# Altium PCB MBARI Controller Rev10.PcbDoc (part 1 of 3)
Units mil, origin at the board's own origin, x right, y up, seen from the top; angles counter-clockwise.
Board outline 10420.2 x 10420.2 mil, 2 copper layers (Top Layer, Bottom Layer); 284 components, 200 nets, 1050 pads, 245 vias.
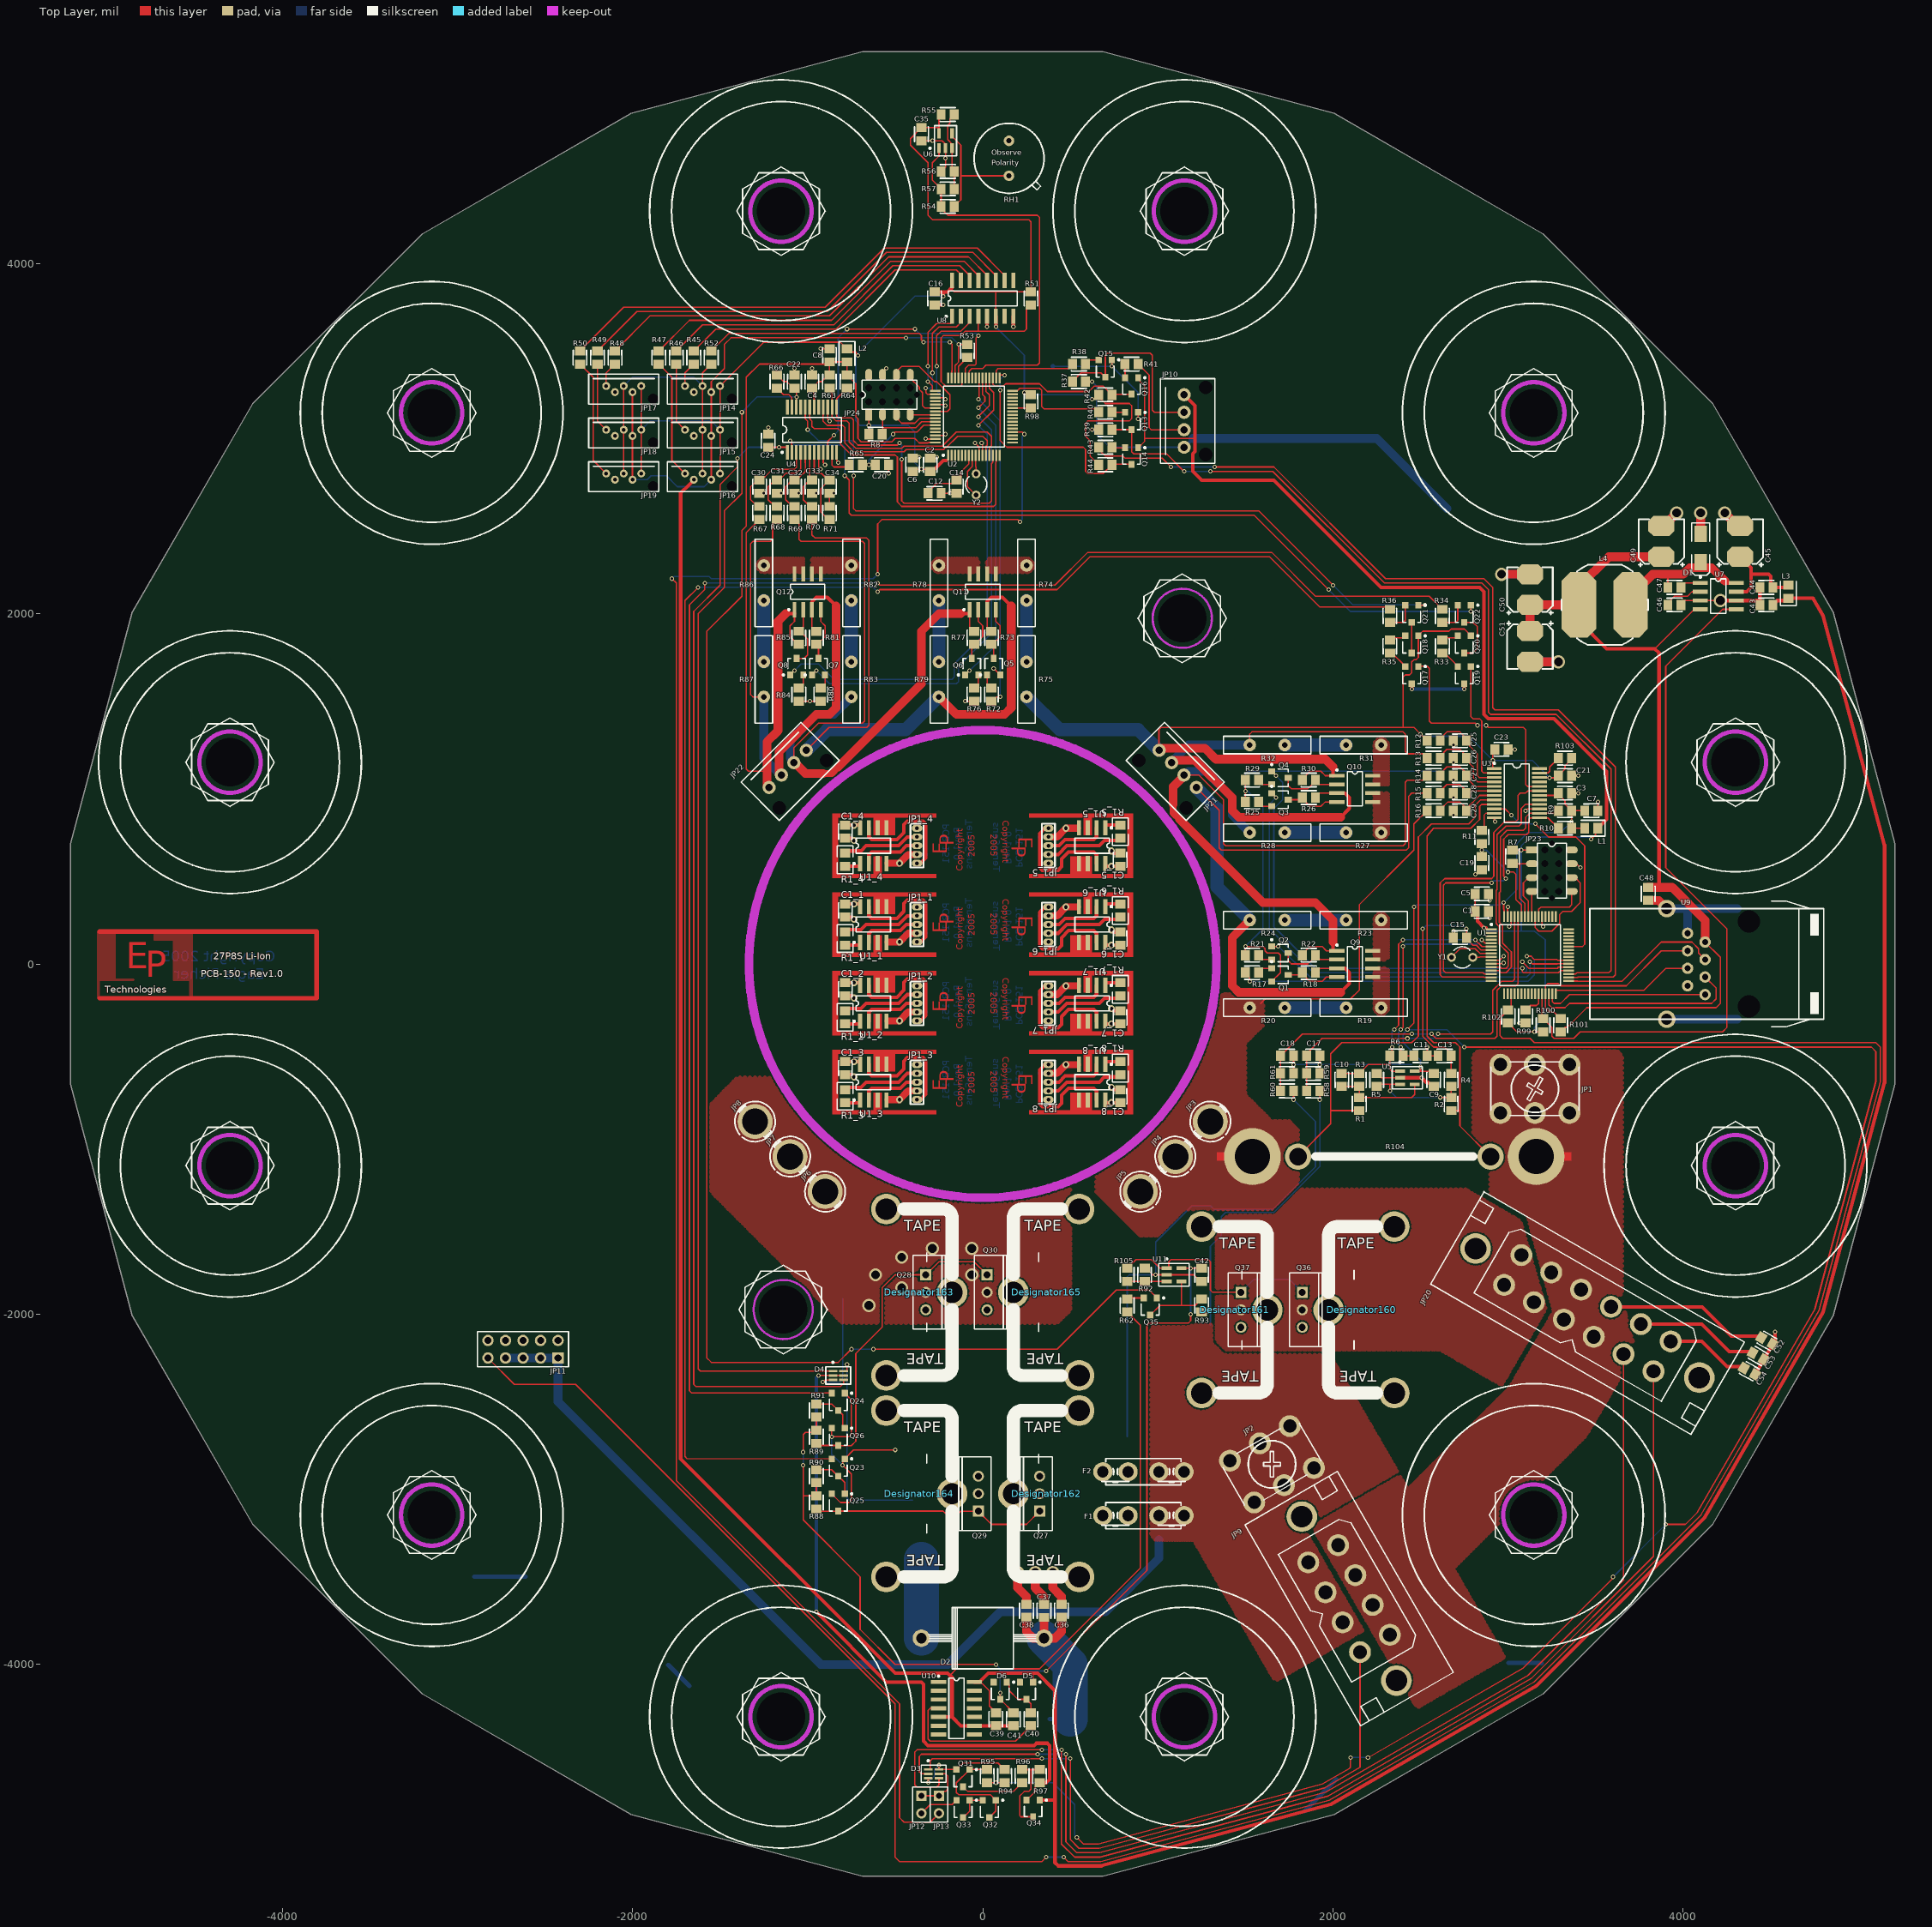
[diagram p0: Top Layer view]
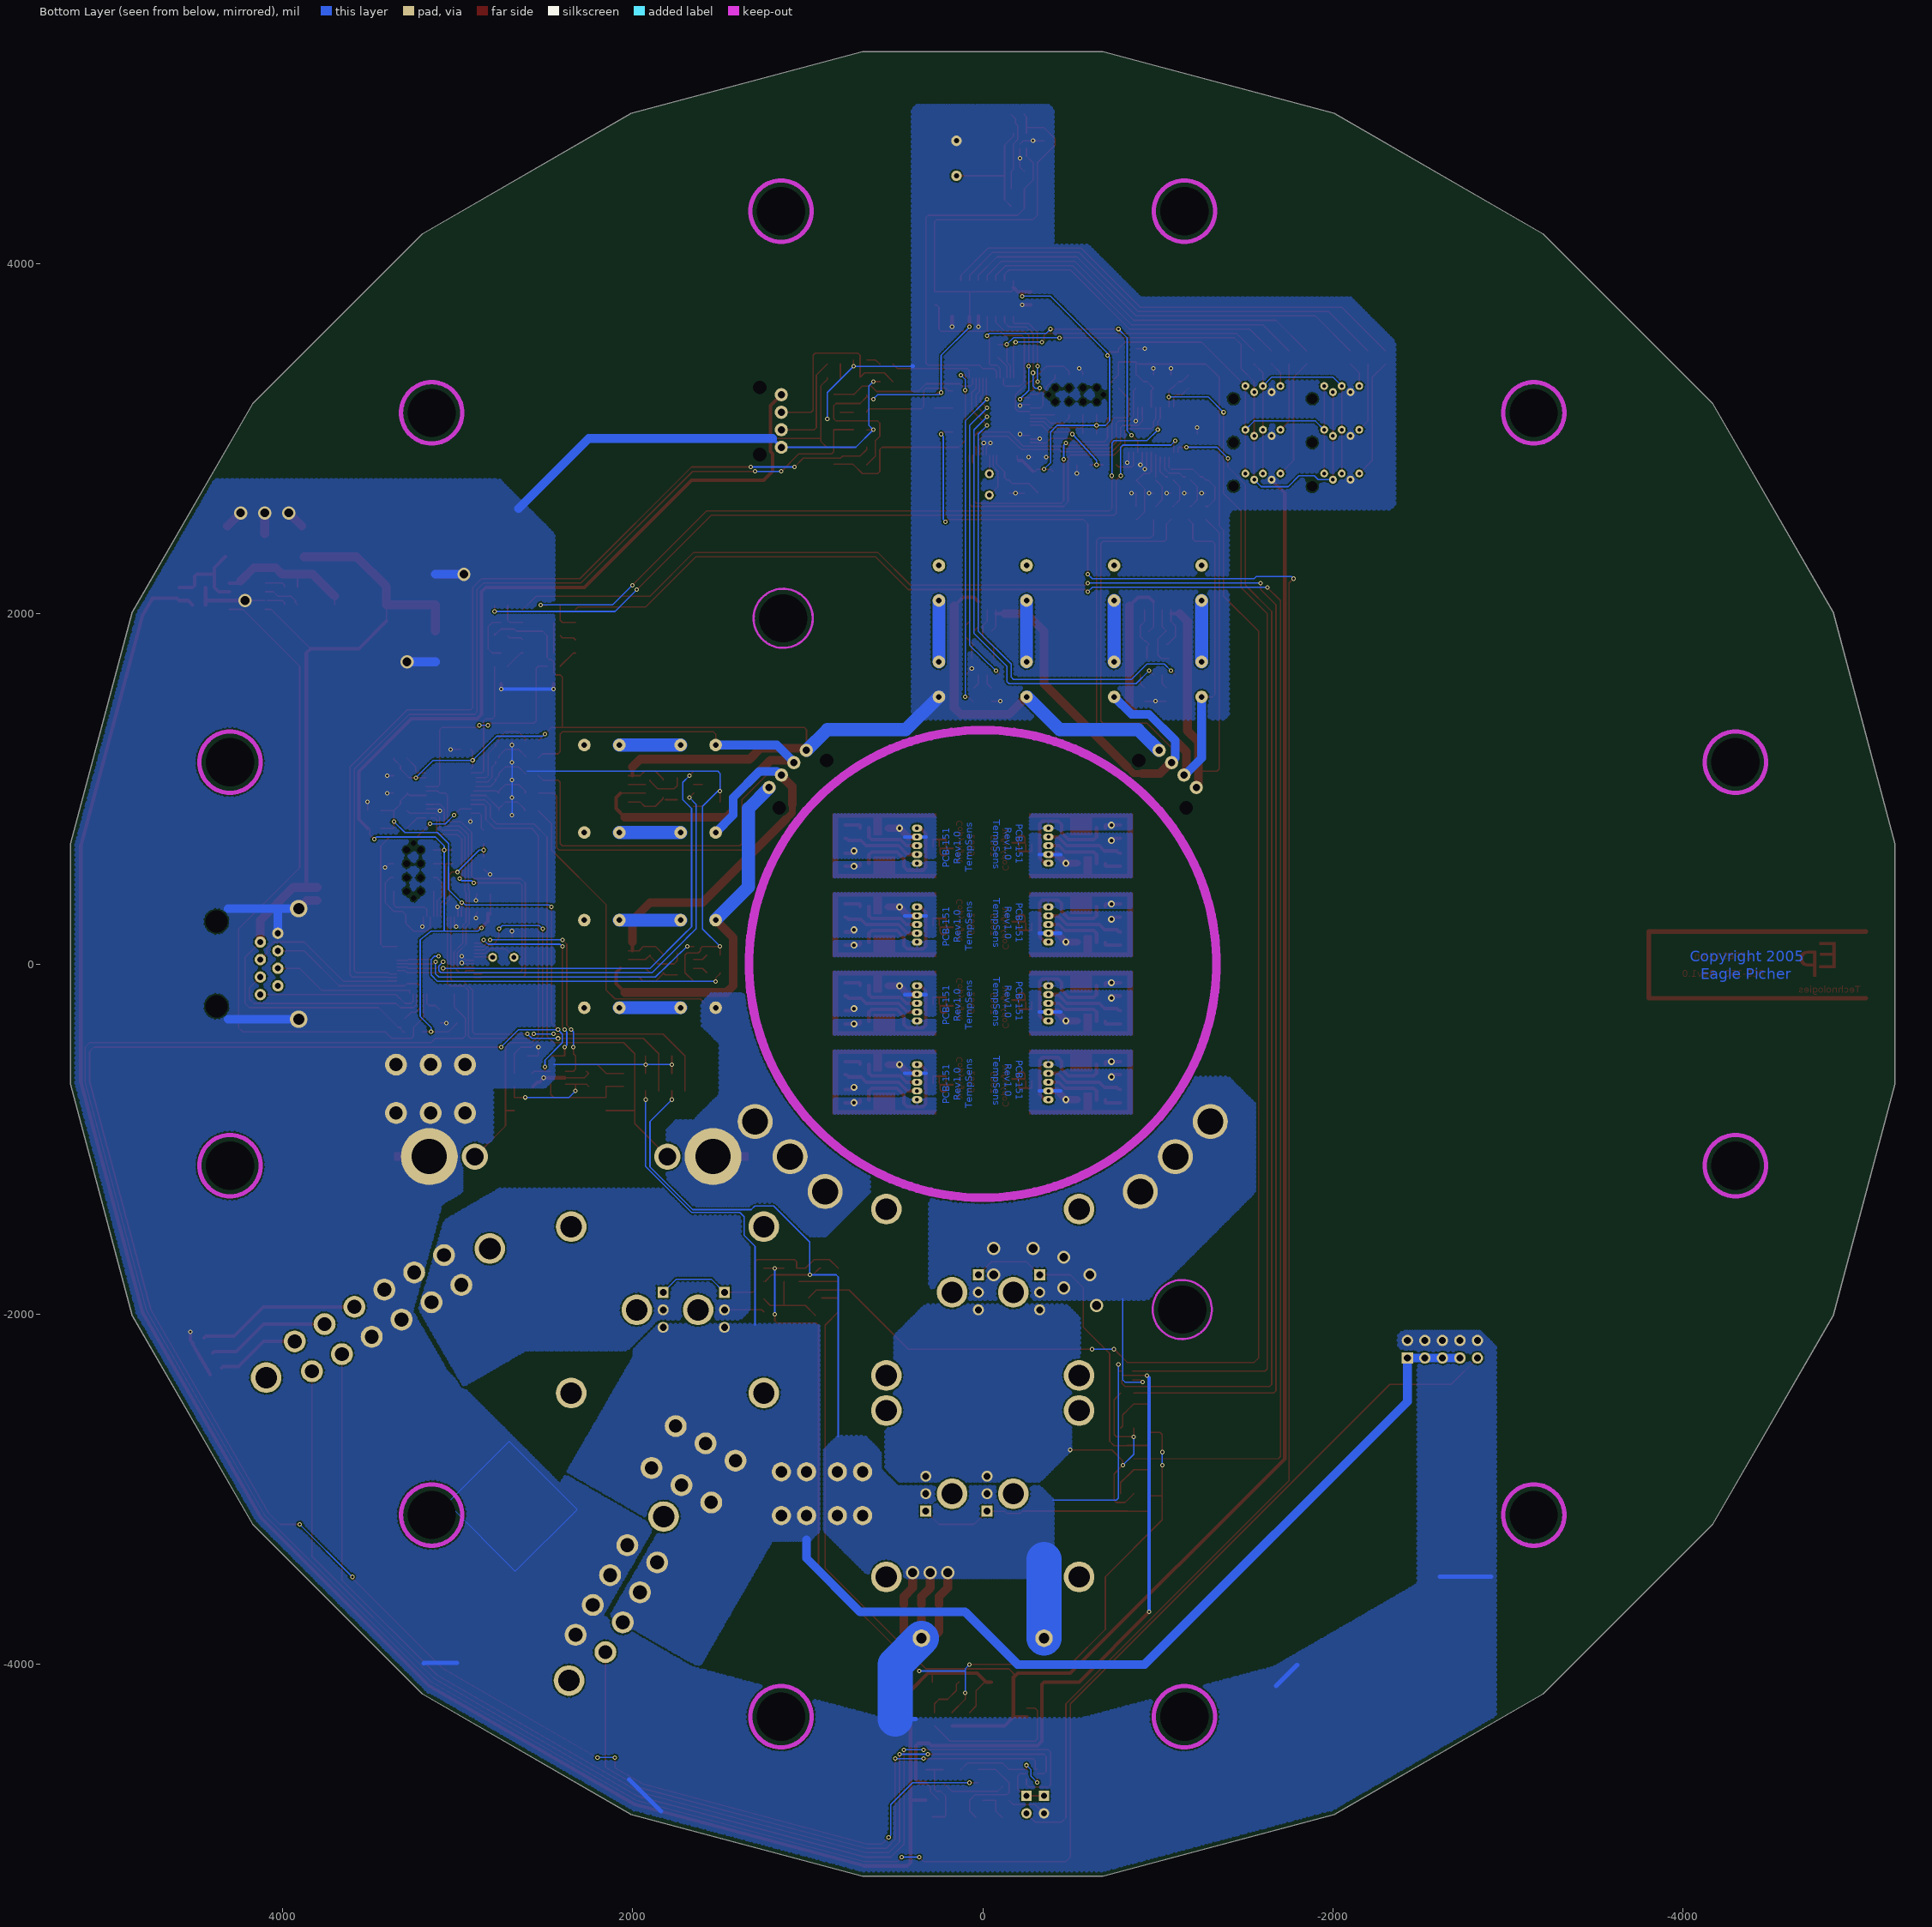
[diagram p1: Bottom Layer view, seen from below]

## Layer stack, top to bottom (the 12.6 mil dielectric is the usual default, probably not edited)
Top Layer: signal copper 1.4
Dielectric: dielectric 12.6, FR-4, Dk 4.8
Bottom Layer: signal copper 1.4

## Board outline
-4854.71,-2011.6 cw(c-4850.37,-2009.09) -4855.12,-2010.67 cw(c-4850.37,-2009.09) -4855.21,-2010.39 -5209.93,-686.56 cw(c-5205.09,-685.26) -5210.1,-685.26 ccw(c-5205.09,-685.26) -5209.93,-686.56 -5210.1,-685.26 -5210.1,685.26 cw(c-5205.09,685.26) -5209.92,686.58 -4855.21,2010.39 cw(c-4850.37,2009.09) -4854.7,2011.62 -4169.45,3198.5 cw(c-4165.1,3196) -4168.65,3199.54 cw(c-4165.1,3196) -4168.63,3199.56 -4168.65,3199.54 -3199.54,4168.65 cw(c-3196,4165.1) -3198.48,4169.46 -2011.6,4854.71 cw(c-2009.09,4850.37) -2010.67,4855.12 cw(c-2009.09,4850.37) -2010.39,4855.21 -686.56,5209.93 cw(c-685.26,5205.08) -685.26,5210.1 ccw(c-685.26,5205.08) -686.56,5209.93 -685.26,5210.1 685.26,5210.1 cw(c685.26,5205.08) 686.58,5209.92 2010.39,4855.21 cw(c2009.09,4850.37) 2011.62,4854.7 3198.5,4169.45 cw(c3196,4165.1) 3199.54,4168.65 cw(c3196,4165.1) 3199.56,4168.63 3199.54,4168.65 4168.65,3199.54 cw(c4165.1,3196) 4169.46,3198.48 4854.71,2011.6 cw(c4850.37,2009.09) 4855.21,2010.37 4855.21,2010.39 ccw(c4850.37,2009.09) 4854.71,2011.6 4855.21,2010.37 5209.93,686.56 cw(c5205.08,685.26) 5210.1,685.26 ccw(c5205.08,685.26) 5209.93,686.56 5210.1,685.26 5210.1,-685.26 cw(c5205.08,-685.26) 5209.95,-686.48 cw(c5205.08,-685.26) 5209.93,-686.56 5209.93,-686.57 ccw(c5205.08,-685.26) 5209.93,-686.55 5209.93,-686.57 4855.21,-2010.39 cw(c4850.37,-2009.09) 4854.7,-2011.62 4854.71,-2011.6 ccw(c4850.37,-2009.09) 4855.21,-2010.39 4854.7,-2011.62 4169.45,-3198.5 cw(c4165.1,-3196) 4168.65,-3199.54 ccw(c4165.1,-3196) 4169.45,-3198.5 4168.65,-3199.54 cw(c4165.1,-3196) 4168.63,-3199.56 4168.65,-3199.54 3199.54,-4168.65 cw(c3196,-4165.1) 3198.48,-4169.46 3198.5,-4169.45 ccw(c3196,-4165.1) 3199.54,-4168.65 3198.48,-4169.46 2011.6,-4854.71 cw(c2009.09,-4850.37) 2010.67,-4855.12 ccw(c2009.09,-4850.37) 2011.6,-4854.71 2010.67,-4855.12 cw(c2009.09,-4850.37) 2010.39,-4855.21 ccw(c2009.09,-4850.37) 2010.67,-4855.12 2010.39,-4855.21 686.56,-5209.93 cw(c685.26,-5205.09) 685.26,-5210.1 ccw(c685.26,-5205.09) 686.56,-5209.93 685.26,-5210.1 -685.26,-5210.1 cw(c-685.26,-5205.09) -686.58,-5209.92 -2010.39,-4855.21 cw(c-2009.09,-4850.37) -2011.62,-4854.7 -3198.5,-4169.45 cw(c-3196,-4165.1) -3199.54,-4168.65 cw(c-3196,-4165.1) -3199.56,-4168.63 -3199.54,-4168.65 -4168.65,-3199.54 cw(c-4165.1,-3196) -4169.46,-3198.48

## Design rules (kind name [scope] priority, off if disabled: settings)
Clearance "Clearance Overlay" [(OnLayer('Top Overlay'))] p1: gap=-20
Clearance "Clearance U1 & U2" [(InComponent('U1')) OR (InComponent('U2')) vs (InComponent('U1')) OR (InComponent('U2'))] p2: gap=7.5
Clearance [All] p3: gap=8
ComponentClearance [All] p1: gap=10 collisioncheckmode=0
HoleSize [All] p1: absolutevalues=TRUE maxlimit=275 minlimit=15 maxpercent=80.000 minpercent=20.000
PlaneClearance [All] p1: clearance=35
PolygonConnect [All] p1: connectstyle=Direct reliefconductorwidth=10 reliefentries=4 polygonreliefangle="90 Angle"
RoomDefinition "MBARI Controller Rev10b" [InComponentClass('MBARI Controller Rev10b')] p1: confinementstyle=ConfineIn formatcopy=TRUE outline -7000,-7000 -5000,-7000 -5000,-6000 -7000,-6000
RoutingCorners [All] p1: cornerstyle=45-Degree minsetback=12.5 maxsetback=100
RoutingVias [All] p1: holewidth=15 width=25 viastyle="Through Hole" minholewidth=15 minwidth=25 maxholewidth=100 maxwidth=50
SolderMaskExpansion [All] p1: expansion=4
TestPointUsage [All] p1: valid=0 allowmultiple=FALSE
Testpoint [All] p1: side=15 testpointundercomponent=TRUE minsize=40 maxsize=100 preferedsize=60 minholesize=0 maxholesize=40 preferedholesize=32 testpointgrid=1 style=1023 order=1234567890
Width [All] p1: maxlimit=200 minlimit=8 preferedwidth=8
14 further rules are at their usual default settings.

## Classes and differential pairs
component class "MBARI Controller Rev10a": C1 C2 C3 C4 C5 C6 C7 C8 C9 C10 C11 C12 C13 C14 C15 C16 C17 C18 C19 C20 C21 C22 C23 C24 C25 C26 C27 C28 C29 C30 C31 C32 C33 C34 C35 C36 C37 C38 C39 C40 C41 C42 C43 C44 C45 C46 C47 C48 C49 C50 C51 C52 C53 C54 D1 D2 D3 D4 D5 D6 F1 F2 JP1 JP2 JP3 JP4 JP5 JP6 JP7 JP8 JP9 JP10 JP11 JP12 JP13 JP14 JP15 JP16 JP17 JP18 JP19 JP20 JP20x JP21 JP22 JP23 JP24 L1 L2 L3 L4 Q1 Q2 Q3 Q4 Q5 Q6 Q7 Q8 Q9 Q10 Q11 Q12 Q13 Q14 Q15 Q16 Q17 Q18 Q19 Q20 Q21 Q22 Q23 Q24 Q25 Q26 Q27 Q28 Q29 Q30 Q31 Q32 Q33 Q34 Q35 Q36 Q37 R1 R2 R3 R4 R5 R6 R7 R8 R9 R10 R11 R12 R13 R14 R15 R16 R17 R18 R19 R20 R21 R22 R23 R24 R25 R26 R27 R28 R29 R30 R31 R32 R33 R34 R35 R36 R37 R38 R39 R40 R41 R42 R43 R44 R45 R46 R47 R48 R49 R50 R51 R52 R53 R54 R55 R56 R57 R58 R59 R60 R61 R62 R63 R64 R65 R66 R67 R68 R69 R70 R71 R72 R73 R74 R75 R76 R77 R78 R79 R80 R81 R82 R83 R84 R85 R86 R87 R88 R89 R90 R91 R92 R93 R94 R95 R96 R97 R98 R99 R100 R101 R102 R103 R104 R105 RH1 U1 U2 U3 U4 U5 U6 U7 U8 U9 U10 U11 Y1 Y2

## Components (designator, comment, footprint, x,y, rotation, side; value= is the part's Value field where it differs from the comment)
C1 "C0805" 0805 2850,300 r180 top
C1_1 "C0805" 0805 -785,305 r90 top (schematic designator C1)
C1_2 "C0805" 0805 -785,-145 r90 top (schematic designator C1)
C1_3 "C0805" 0805 -785,-595 r90 top (schematic designator C1)
C1_4 "C0805" 0805 -785,755 r90 top (schematic designator C1)
C1_5 "C0805" 0805 785,595 r270 top (schematic designator C1)
C1_6 "C0805" 0805 785,145 r270 top (schematic designator C1)
C1_7 "C0805" 0805 785,-305 r270 top (schematic designator C1)
C1_8 "C0805" 0805 785,-755 r270 top (schematic designator C1)
C2 "C0805" 0805 -300,2850 r270 top
C3 "C0805" 0805 3325,975 r180 top
C4 "C0805" 0805 -975,3325 r270 top
C5 "C0805" 0805 2850,400 r0 top
C6 "C0805" 0805 -400,2850 r90 top
C7 "C0805" 0805 3475,875 r0 top
C8 "C0805" 0805 -875,3475 r90 top
C9 "C0805" 0805 2575,-662.5 r90 top locked
C10 "C0805" 0805 2050,-662.5 r90 top locked
C11 "C0805" 0805 2500,-525 r0 top
C12 "C0805" 0805 -275,2687.5 r0 top
C13 "C0805" 0805 2637.5,-525 r180 top locked
C14 "C0805" 0805 -150,2725 r90 top
C15 "C0805" 0805 2725,150 r0 top
C16 "C0805" 0805 -275,3800.1 r90 top
C17 "C0805" 0805 1887.6,-525 r180 top locked
C18 "C0805" 0805 1737.6,-525 r180 top locked
C19 "C0805" 0805 2850,575 r90 top
C20 "C0805" 0805 -574.9,2850 r180 top
C21 "C0805" 0805 3325.1,1075 r180 top
C22 "C0805" 0805 -1075,3325 r270 top
C23 "C0805" 0805 2962.4,1225 r180 top locked
C24 "C0805" 0805 -1225,2987.4 r270 top locked
C25 "C0805" 0805 2725,1275 r0 top
C26 "C0805" 0805 2725,1175 r0 top
C27 "C0805" 0805 2725,1075 r0 top
C28 "C0805" 0805 2725,975 r0 top
C29 "C0805" 0805 2725,875 r0 top
C30 "C0805" 0805 -1275,2725 r90 top locked
C31 "C0805" 0805 -1175,2725 r90 top locked
C32 "C0805" 0805 -1075,2725 r90 top locked
C33 "C0805" 0805 -975,2725 r90 top locked
C34 "C0805" 0805 -875,2725 r90 top locked
C35 "C0805" 0805 -350,4737.4 r90 top
C36 "C0805" 0805 450,-3693.65 r90 top
C37 "C0805" 0805 350,-3693.85 r90 top
C38 "C0805" 0805 250,-3693.65 r90 top
C39 "C0805" 0805 75,-4312.6 r90 top locked
C40 "C0805" 0805 275,-4312.4 r270 top locked
C41 "C0805" 0805 175,-4312.4 r270 top locked
C42 "C0805" 0805 1250,-1774.9 r90 top
C43 "C0805" 0805 4475,2050 r0 top locked
C44 "C0805" 0805 4475,2150 r0 top locked
C45 "Cap Pol2" "CAP S/M 6.3DIA" 4325,2325 r90 top locked
C46 "C0805" 0805 3950,2050 r0 top locked
C47 "C0805" 0805 3950,2150 r180 top locked
C48 "C0805" 0805 3800,400 r90 top locked
C49 "Cap Pol2" "CAP S/M 6.3DIA" 3875,2325 r90 top locked
C50 "Cap Pol2" "CAP S/M 6.3DIA" 3125,2050 r90 top locked
C51 "Cap Pol2" "CAP S/M 6.3DIA" 3125,1900 r270 top locked
C52 "C0805" 0805 4478.66,-2152.74 r150 top
C53 "C0805" 0805 4428.66,-2239.34 r150 top
C54 "C0805" 0805 4378.66,-2325.95 r150 top
D1 "IR 10MQ060N" SMA 4100,2375 r270 top locked
D2 "D Zener" P600 350,-3850 r180 top locked
D3 "" SO-G6/Z2.8 -280.51,-4624.41 r270 top locked
D4 "" SO-G6/Z2.8 -825,-2350 r270 top
D5 "Diode BAS70" SO-G3/C2.5 250,-4150 r180 top
D6 "Diode BAS70" SO-G3/C2.5 100,-4150 r180 top
Designator160 "Comment" "TO220 576602" 2000,-1975 r90 top locked
Designator161 "Comment" "TO220 576602" 1600,-1975 r270 top locked
Designator162 "Comment" "TO220 576602" 200,-3025 r90 top locked
Designator163 "Comment" "TO220 576602" -200,-1875 r270 top locked
Designator164 "Comment" "TO220 576602" -200,-3025 r270 top locked
Designator165 "Comment" "TO220 576602" 200,-1875 r90 top locked
F1 "" "FUSECLIP MINI PCB" 918,-3150 r180 top locked
F2 "" "FUSECLIP MINI PCB" 918,-2900 r180 top locked
JP1 "Socket" "Terminal - screw" 2956,-851 r90 top locked
JP1_1 "HEADER 5X1" "Header 5x.05" -375,325 r270 top (schematic designator JP1)
JP1_2 "HEADER 5X1" "Header 5x.05" -375,-125 r270 top (schematic designator JP1)
JP1_3 "HEADER 5X1" "Header 5x.05" -375,-575 r270 top (schematic designator JP1)
JP1_4 "HEADER 5X1" "Header 5x.05" -375,775 r270 top (schematic designator JP1)
JP1_5 "HEADER 5X1" "Header 5x.05" 375,575 r90 top (schematic designator JP1)
JP1_6 "HEADER 5X1" "Header 5x.05" 375,125 r90 top (schematic designator JP1)
JP1_7 "HEADER 5X1" "Header 5x.05" 375,-325 r90 top (schematic designator JP1)
JP1_8 "HEADER 5X1" "Header 5x.05" 375,-775 r90 top (schematic designator JP1)
JP2 "Socket" "Terminal - screw" 1550,-3075 r120 top locked
JP3 "TERMINAL 10AWG" "Terminal 10AWG crimp" 1300,-900 r315 top locked
JP4 "TERMINAL 10AWG" "Terminal 10AWG crimp" 1100,-1100 r315 top locked
JP5 "TERMINAL 10AWG" "Terminal 10AWG crimp" 900,-1300 r315 top locked
JP6 "TERMINAL 10AWG" "Terminal 10AWG crimp" -900,-1300 r225 top locked
JP7 "TERMINAL 10AWG" "Terminal 10AWG crimp" -1100,-1100 r225 top locked
JP8 "TERMINAL 10AWG" "Terminal 10AWG crimp" -1300,-900 r225 top locked
JP9 "Female" PLB08F3 2240,-3879.79 r120 top locked (schematic designator JP21)
JP10 "HEADER 4 SHROUDED" "MTA-100-4 Shrouded" 1150,3250 r90 top
JP11 "Header 5X2" "Header 5x2V" -2425,-2250 r180 top locked (schematic designator JP22)
JP12 "Header 2" HDR1X2 -350,-4750 r270 top locked
JP13 "Header 2" HDR1X2 -250,-4750 r270 top locked
JP14 "" "Header 5 MTA50" -1500,3300 r180 top locked
JP15 "" "Header 5 MTA50" -1500,3050 r180 top locked
JP16 "" "Header 5 MTA50" -1500,2800 r180 top locked
JP17 "" "Header 5 MTA50" -1950,3300 r180 top locked
JP18 "" "Header 5 MTA50" -1950,3050 r180 top locked
JP19 "" "Header 5 MTA50" -1950,2800 r180 top locked
JP20 "Female" PLB12F3 3879.79,-2240 r150 top locked
JP21 "HEADER 4 SHROUDED" "MTA-100-4 Shrouded" 1219.76,1007.63 r315 top locked
JP22 "HEADER 4 SHROUDED" "MTA-100-4 Shrouded" -1007.63,1219.76 r45 top locked
JP23 "HEADER 8F LOW" "Header 4x2 2mm fem low" 3136.81,650.59 r270 top
JP24 "HEADER 8F LOW" "Header 4x2 2mm fem low" -650.59,3136.81 r0 top
L1 "LQM21FN100N00L" CC2012-0805 3475,775 r180 top
L2 "LQM21FN100N00L" CC2012-0805 -775,3475 r270 top
L3 "LQM21FN100N00L" CC2012-0805 4600,2125 r90 top locked
L4 "Inductor Iron" CDR125 3700,2050 r180 top locked
Q1 "BC847C" SOT23 1697.24,-62.4 r270 top locked
Q2 "BC847C" SOT23 1697.24,62.4 r270 top locked
Q3 "BC847C" SOT23 1697.24,937.6 r270 top locked
Q4 "BC847C" SOT23 1697.24,1062.6 r270 top locked
Q5 "BC847C" SOT23 62.4,1697.24 r0 top locked
Q6 "BC847C" SOT23 -62.6,1697.24 r0 top locked
Q7 "BC847C" SOT23 -937.6,1697.24 r0 top locked
Q8 "BC847C" SOT23 -1062.4,1697.24 r0 top locked
Q9 "IRF7328" SO-8 2125,0 r270 top locked
Q10 "IRF7328" SO-8 2125,1000 r270 top locked
Q11 "IRF7328" SO-8 0,2125 r0 top locked
Q12 "IRF7328" SO-8 -1000,2125 r0 top locked
Q13 "BC856BLT1" 318-08 850,3100 r180 top locked
Q14 "BC847C" SOT23 850,2900 r180 top locked
Q15 "BC856BLT1" 318-08 700,3400 r180 top locked
Q16 "BC847C" SOT23 850,3300 r180 top locked
Q17 "BC856BLT1" 318-08 2450,1649.21 r180 top locked
Q18 "BC847CLT1" 318-08 2450,1824.21 r180 top locked
Q19 "BC856BLT1" 318-08 2750,1649.21 r180 top locked
Q20 "BC847CLT1" 318-08 2750,1824.21 r180 top locked
Q21 "BC856BLT1" 318-08 2450,1999.21 r180 top locked
Q22 "BC856BLT1" 318-08 2750,1999.21 r180 top locked
Q23 "BC847CLT1" 318-08 -825,-2875 r180 top
Q24 "BC847CLT1" 318-08 -825,-2500 r180 top
Q25 "BC847CLT1" 318-08 -825,-3075 r180 top
Q26 "BC847CLT1" 318-08 -825,-2700 r180 top
Q27 "IRF2804" TO-220AB 325,-3025 r90 top locked
Q28 "IRF2804" TO-220AB -325,-1875 r270 top locked
Q29 "IRF2804" TO-220AB -25,-3025 r90 top locked
Q30 "IRF2804" TO-220AB 25,-1875 r270 top locked
Q31 "BC847CLT1" 318-08 -112.6,-4649.21 r180 top locked
Q32 "BC847CLT1" 318-08 37.6,-4824.21 r180 top locked
Q33 "BC847CLT1" 318-08 -112.4,-4824.21 r180 top locked
Q34 "BSS84LT1" SOT23 287.6,-4822.24 r180 top locked
Q35 "BC847CLT1" 318-08 956.25,-1956.25 r180 top
Q36 "IRF2804" TO-220AB 1825,-1975 r270 top locked
Q37 "IRF2804" TO-220AB 1475,-1975 r270 top locked
R1 "ERJ6GE" C0805 2150,-800 r270 top locked
R1_1 "ERJ6GE" 6-0805 -785,145 r90 top (schematic designator R1)
R1_2 "ERJ6GE" 6-0805 -785,-305 r90 top (schematic designator R1)
R1_3 "ERJ6GE" 6-0805 -785,-755 r90 top (schematic designator R1)
R1_4 "ERJ6GE" 6-0805 -785,595 r90 top (schematic designator R1)
R1_5 "ERJ6GE" 6-0805 785,755 r270 top (schematic designator R1)
R1_6 "ERJ6GE" 6-0805 785,305 r270 top (schematic designator R1)
R1_7 "ERJ6GE" 6-0805 785,-145 r270 top (schematic designator R1)
R1_8 "ERJ6GE" 6-0805 785,-595 r270 top (schematic designator R1)
R2 "ERJ6GE" C0805 2675,-800 r270 top
R3 "ERJ6GE" C0805 2150,-662.5 r270 top locked
R4 "ERJ6GE" C0805 2675,-662.5 r270 top locked
R5 "ERJ6GE" C0805 2250,-662.5 r90 top locked
R6 "ERJ6GE" C0805 2362.5,-525 r180 top
R7 "ERJ6GE" C0805 3025,612.6 r270 top
R8 "ERJ6GE" C0805 -612.4,3025 r0 top locked
R9 "ERJ6GE" C0805 3324.9,875 r180 top
R10 "ERJ6GE" C0805 3325.1,775 r180 top
R11 "ERJ6GE" C0805 2850,725 r270 top
R12 "ERJ6GE" C0805 2575,1275 r0 top locked
R13 "ERJ6GE" C0805 2575,1175 r0 top locked
R14 "ERJ6GE" C0805 2575,1075 r0 top locked
R15 "ERJ6GE" C0805 2575,975 r0 top locked
R16 "ERJ6GE" C0805 2575,875 r0 top locked
R17 "ERJ6GE" C0805 1537.4,-50 r0 top locked
R18 "ERJ6GE" C0805 1862.6,-50 r0 top locked
R19 "" "Resistor 5W - ceramic" 2275,-250 r180 top locked
R20 "" "Resistor 5W - ceramic" 1725,-250 r180 top locked
R21 "ERJ6GE" C0805 1537.6,50 r0 top locked
R22 "ERJ6GE" C0805 1862.6,50 r180 top locked
R23 "" "Resistor 5W - ceramic" 2275,250 r180 top locked
R24 "" "Resistor 5W - ceramic" 1725,250 r180 top locked
R25 "ERJ6GE" C0805 1537.4,925.2 r0 top locked
R26 "ERJ6GE" C0805 1862.6,950 r0 top locked
R27 "" "Resistor 5W - ceramic" 2275,750 r180 top locked
R28 "" "Resistor 5W - ceramic" 1725,750 r180 top locked
R29 "ERJ6GE" C0805 1537.4,1050.2 r0 top locked
R30 "ERJ6GE" C0805 1862.6,1050 r180 top locked
R31 "" "Resistor 5W - ceramic" 2275,1250 r180 top locked
R32 "" "Resistor 5W - ceramic" 1725,1250 r180 top locked
R33 "ERJ6GE" C0805 2625,1812.4 r90 top locked
R34 "ERJ6GE" C0805 2625,1987.4 r90 top locked
R35 "ERJ6GE" C0805 2325,1812.4 r90 top locked
R36 "ERJ6GE" C0805 2325,1987.4 r90 top locked
R37 "ERJ6GE" C0805 550,3325 r180 top locked
R38 "ERJ6GE" C0805 550,3425 r180 top locked
R39 "ERJ6GE" C0805 700,3050 r0 top locked
R40 "ERJ6GE" C0805 700,3150 r180 top locked
R41 "ERJ6GE" C0805 850,3425 r0 top locked
R42 "ERJ6GE" C0805 700,3250 r180 top locked
R43 "ERJ6GE" C0805 700,2950 r180 top locked
R44 "ERJ6GE" C0805 700,2850 r180 top locked
R45 "ERJ6GE" C0805 -1650,3462.4 r270 top
R46 "ERJ6GE" C0805 -1750,3462.4 r270 top
R47 "ERJ6GE" C0805 -1850,3462.4 r270 top
R48 "ERJ6GE" C0805 -2100,3462.4 r270 top
R49 "ERJ6GE" C0805 -2200,3462.4 r270 top
R50 "ERJ6GE" C0805 -2300,3462.4 r270 top
R51 "ERJ6GE" C0805 275,3800 r270 top
R52 "ERJ6GE" C0805 -1550,3462.4 r270 top
R53 "ERJ6GE" C0805 -87.5,3500 r90 top
R54 "ERJ6GE" C0805 -200,4325 r180 top
R55 "ERJ6GE" C0805 -200,4850 r180 top
R56 "ERJ6GE" C0805 -200,4525 r0 top
R57 "ERJ6GE" C0805 -200,4425 r180 top
R58 "ERJ6GE" C0805 1887.4,-725 r0 top locked
R59 "ERJ6GE" C0805 1887.4,-625 r180 top locked
R60 "ERJ6GE" C0805 1737.6,-725 r0 top locked
R61 "ERJ6GE" C0805 1737.6,-625 r180 top locked
R62 "ERJ6GE" C0805 825,-1950 r270 top
R63 "ERJ6GE" C0805 -875,3325 r270 top
R64 "ERJ6GE" C0805 -775,3325.1 r270 top
R65 "ERJ6GE" C0805 -725.1,2850 r0 top
R66 "ERJ6GE" C0805 -1175,3325.1 r90 top
R67 "ERJ6GE" C0805 -1275,2575 r90 top locked
R68 "ERJ6GE" C0805 -1175,2575 r90 top locked
R69 "ERJ6GE" C0805 -1075,2575 r90 top locked
R70 "ERJ6GE" C0805 -975,2575 r90 top locked
R71 "ERJ6GE" C0805 -875,2575 r270 top locked
R72 "ERJ6GE" C0805 50,1537.4 r90 top locked
R73 "ERJ6GE" C0805 50,1862.4 r90 top locked
R74 "" "Resistor 5W - ceramic" 250,2275 r270 top locked
R75 "" "Resistor 5W - ceramic" 250,1725 r270 top locked
R76 "ERJ6GE" C0805 -50,1537.4 r90 top locked
R77 "ERJ6GE" C0805 -50,1862.4 r90 top locked
R78 "" "Resistor 5W - ceramic" -250,2275 r270 top locked
R79 "" "Resistor 5W - ceramic" -250,1725 r270 top locked
R80 "ERJ6GE" C0805 -925,1537.6 r90 top locked
R81 "ERJ6GE" C0805 -950,1862.4 r90 top locked
R82 "" "Resistor 5W - ceramic" -750,2275 r270 top locked
R83 "" "Resistor 5W - ceramic" -750,1725 r270 top locked
R84 "ERJ6GE" C0805 -1050,1537.6 r90 top locked
R85 "ERJ6GE" C0805 -1050,1862.6 r270 top locked
R86 "" "Resistor 5W - ceramic" -1250,2275 r270 top locked
R87 "" "Resistor 5W - ceramic" -1250,1725 r270 top locked
R88 "ERJ6GE" C0805 -950,-3075 r90 top
R89 "ERJ6GE" C0805 -950,-2700 r90 top
R90 "ERJ6GE" C0805 -950,-2925 r270 top
R91 "ERJ6GE" C0805 -950,-2550 r270 top
R92 "ERJ6GE" C0805 925,-1775.1 r270 top
R93 "ERJ6GE" C0805 1250,-1950 r90 top
R94 "ERJ6GE" C0805 125,-4637.6 r270 top locked
R95 "ERJ6GE" C0805 25,-4637.6 r270 top locked
R96 "ERJ6GE" C0805 225,-4637.6 r90 top locked
R97 "ERJ6GE" C0805 325,-4637.6 r270 top locked
R98 "ERJ6GE" C0805 275,3212.4 r270 top
R99 "ERJ6GE" C0805 3100,-299.9 r90 top
R100 "ERJ6GE" C0805 3200,-349.9 r270 top locked
R101 "ERJ6GE" C0805 3300,-349.9 r270 top locked
R102 "ERJ6GE" C0805 3000,-299.9 r90 top
R103 "ERJ6GE" C0805 3325.1,1175 r0 top
R104 "Resistor Shunt 4-term" "Shunt PCB-BH-50-50" 2350,-1100 r180 top locked
R105 "ERJ6GE" C0805 825,-1774.9 r90 top
RH1 "HS1101" HS1101 150,4500 r90 top
U1 "" F-QFP10x10-G64/N 3125,50 r0 top locked
U1_1 "*" SO-G8 -625,225 r0 top (schematic designator U1)
U1_2 "*" SO-G8 -625,-225 r0 top (schematic designator U1)
U1_3 "*" SO-G8 -625,-675 r0 top (schematic designator U1)
U1_4 "*" SO-G8 -625,675 r0 top (schematic designator U1)
U1_5 "*" SO-G8 625,675 r180 top (schematic designator U1)
U1_6 "*" SO-G8 625,225 r180 top (schematic designator U1)
U1_7 "*" SO-G8 625,-225 r180 top (schematic designator U1)
U1_8 "*" SO-G8 625,-675 r180 top (schematic designator U1)
U2 "" F-QFP10X10-G64/N -50,3125 r90 top locked
U3 "BQ29312" SSO-G24/P.65 3050,975 r270 top locked
U4 "BQ29312" SSO-G24/P.65 -975,3050 r0 top locked
U5 "LM7131ACM5" MA05A 2425,-650 r270 top locked
U6 "LM7131ACM5" MA05A -212.5,4700 r0 top locked
U7 "Max5033" SO-G8 4200,2100 r270 top locked
U8 "MC74VHC138D" 751B-05 0,3800 r0 top locked
U9 "XPort" XPort 4025,175 r180 top locked
U10 "ICL7662CBD" NSO14 -150,-4250 r270 top locked
U11 "MAX9075EUK-T" SOT23-5 1092.32,-1775 r270 top
Y1 "32kHz" BCY-W2/D3.1 2737.5,37.5 r270 top locked
Y2 "32kHz" BCY-W2/D3.1 -37.5,2737.5 r0 top locked

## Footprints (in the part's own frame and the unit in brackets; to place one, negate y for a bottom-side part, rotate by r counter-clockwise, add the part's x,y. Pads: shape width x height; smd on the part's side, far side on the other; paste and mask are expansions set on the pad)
6-0805 [mm] "Chip Resistor; Body 2 x 1.2 mm (LxW typ)"
  rect 1.3x1.5 smd: 1(-0.95,0) 2(0.95,0)
  silkscreen extent -2,-1.15 2,1.15
318-08 [mm] "SOT-23; 3 Leads; Body 3.0 x 2.6 mm, inc. leads (LxW max)"
  rect 0.9x0.95 smd: 1(-0.95,-1.25) 2(0.95,-1.25) 3(0,1.25)
  silkscreen extent -2.08,-1.37 1.3,1.25
751B-05 [mm] "Small Outline; 16 Leads; Body Width 3.9 mm; Pitch 1.27 mm"
  rect 0.6x2.2 smd: 1(-4.445,-2.6) 2(-3.175,-2.6) 3(-1.905,-2.6) 4(-0.635,-2.6) 5(0.635,-2.6) 6(1.905,-2.6) 7(3.175,-2.6) 8(4.445,-2.6) 9(4.445,2.6) 10(3.175,2.6) 11(1.905,2.6) 12(0.635,2.6) 13(-0.635,2.6) 14(-1.905,2.6) 15(-3.175,2.6) 16(-4.445,2.6)
  silkscreen extent -5.42,-2.72 5,1.1
0805 [mm] "Chip Capacitor; Body 2.0 x 1.2 mm (LxW typ)"
  rect 1.3x1.5 smd: 1(-0.95,0) 2(0.95,0)
  silkscreen extent -1.1,-1 1.1,1
BCY-W2/D3.1 [mm]
  round 1.3 hole 0.7: 1(0,1.55) 2(0,-1.55)
  silkscreen extent -1.55,-1.19 1.55,1.17
C0805 [mm] "Chip Capacitor; Body 2.0 x 1.2 mm (LxW typ)"
  rect 1.3x1.5 smd: 1(-0.95,0) 2(0.95,0)
  silkscreen extent -1.1,-1 1.1,1
"CAP S/M 6.3DIA" [mil] "Panasonic EEV; Nichicon UUD"
  oct 115x150 smd: 1(0,0) 2(175,0)
  silkscreen extent -55,-130 215,130
CC2012-0805 [mm]
  rect 1.3x1.5 smd: 1(-0.95,0) 2(0.95,0)
  silkscreen extent -2,-1.15 1.5,1.15
CDR125 [mil] "Sumida inductor"
  oct 197x374 smd: 1(0,0) 2(295,0)
  silkscreen extent -100,-228 396,228
F-QFP10x10-G64/N [mm]
  rect 1.6x0.3 smd: 1(-5.6,3.75) 2(-5.6,3.25) 3(-5.6,2.75) 4(-5.6,2.25) 5(-5.6,1.75) 6(-5.6,1.25) 7(-5.6,0.75) 8(-5.6,0.25) 9(-5.6,-0.25) 10(-5.6,-0.75) 11(-5.6,-1.25) 12(-5.6,-1.75) 13(-5.6,-2.25) 14(-5.6,-2.75) 15(-5.6,-3.25) 16(-5.6,-3.75) 33(5.6,-3.75) 34(5.6,-3.25) 35(5.6,-2.75) 36(5.6,-2.25) 37(5.6,-1.75) 38(5.6,-1.25) 39(5.6,-0.75) 40(5.6,-0.25) 41(5.6,0.25) 42(5.6,0.75) 43(5.6,1.25) 44(5.6,1.75) 45(5.6,2.25) 46(5.6,2.75) 47(5.6,3.25) 48(5.6,3.75)
  rect 0.3x1.6 smd: 17(-3.75,-5.6) 18(-3.25,-5.6) 19(-2.75,-5.6) 20(-2.25,-5.6) 21(-1.75,-5.6) 22(-1.25,-5.6) 23(-0.75,-5.6) 24(-0.25,-5.6) 25(0.25,-5.6) 26(0.75,-5.6) 27(1.25,-5.6) 28(1.75,-5.6) 29(2.25,-5.6) 30(2.75,-5.6) 31(3.25,-5.6) 32(3.75,-5.6) 49(3.75,5.6) 50(3.25,5.6) 51(2.75,5.6) 52(2.25,5.6) 53(1.75,5.6) 54(1.25,5.6) 55(0.75,5.6) 56(0.25,5.6) 57(-0.25,5.6) 58(-0.75,5.6) 59(-1.25,5.6) 60(-1.75,5.6) 61(-2.25,5.6) 62(-2.75,5.6) 63(-3.25,5.6) 64(-3.75,5.6)
  silkscreen extent -5.72,-4.4 4.4,4.57
F-QFP10X10-G64/N [mm]
  rect 1.6x0.3 smd: 1(-5.6,3.75) 2(-5.6,3.25) 3(-5.6,2.75) 4(-5.6,2.25) 5(-5.6,1.75) 6(-5.6,1.25) 7(-5.6,0.75) 8(-5.6,0.25) 9(-5.6,-0.25) 10(-5.6,-0.75) 11(-5.6,-1.25) 12(-5.6,-1.75) 13(-5.6,-2.25) 14(-5.6,-2.75) 15(-5.6,-3.25) 16(-5.6,-3.75) 33(5.6,-3.75) 34(5.6,-3.25) 35(5.6,-2.75) 36(5.6,-2.25) 37(5.6,-1.75) 38(5.6,-1.25) 39(5.6,-0.75) 40(5.6,-0.25) 41(5.6,0.25) 42(5.6,0.75) 43(5.6,1.25) 44(5.6,1.75) 45(5.6,2.25) 46(5.6,2.75) 47(5.6,3.25) 48(5.6,3.75)
  rect 0.3x1.6 smd: 17(-3.75,-5.6) 18(-3.25,-5.6) 19(-2.75,-5.6) 20(-2.25,-5.6) 21(-1.75,-5.6) 22(-1.25,-5.6) 23(-0.75,-5.6) 24(-0.25,-5.6) 25(0.25,-5.6) 26(0.75,-5.6) 27(1.25,-5.6) 28(1.75,-5.6) 29(2.25,-5.6) 30(2.75,-5.6) 31(3.25,-5.6) 32(3.75,-5.6) 49(3.75,5.6) 50(3.25,5.6) 51(2.75,5.6) 52(2.25,5.6) 53(1.75,5.6) 54(1.25,5.6) 55(0.75,5.6) 56(0.25,5.6) 57(-0.25,5.6) 58(-0.75,5.6) 59(-1.25,5.6) 60(-1.75,5.6) 61(-2.25,5.6) 62(-2.75,5.6) 63(-3.25,5.6) 64(-3.75,5.6)
  silkscreen extent -5.72,-4.4 4.4,4.57
"FUSECLIP MINI PCB" [mil] "Keystone #3544 x2"
  round 110 hole 65: 1(-232,0) 1(-88,0) 2(88,0) 2(232,0)
  silkscreen extent -238,-75 238,75
HDR1X2 [mm] "Connector; Header; 2 Position"
  rect 1.5x1.5 hole 0.9: 1(0,0)
  round 1.5 hole 0.9: 2(2.54,0)
  silkscreen extent -1.27,-1.27 3.81,1.27
"Header 4x2 2mm fem low" [mm] "Molex 87340-0822"
  round 0 hole 0.8: 0(-1,2.875) 0(7,2.875)
  round 0 hole 1 unplated: 0(0,3.875) 0(0,1.875) 0(2,3.875) 0(2,1.875) 0(4,3.875) 0(4,1.875) 0(6,3.875) 0(6,1.875)
  rect 1x1.75 smd: 1(0,0)
  oval 1x1.75 smd: 2(2,0) 3(4,0) 4(6,0) 5(6,5.75) 6(4,5.75) 7(2,5.75) 8(0,5.75)
  silkscreen extent -1,0.78 7,4.97
"Header 5 MTA50" [mil] "AMP MTA-50"
  round 0 hole 60 unplated: 0(-68,73)
  round 45 hole 22: 1(0,0) 2(50,35) 3(100,0) 4(150,35) 5(200,0)
  silkscreen extent -100,-67 300,103
"Header 5x2V" [mil] "Sullins PPTC052LFBN etc."
  rect 65x65 hole 40: 1(0,0)
  round 65 hole 40: 2(0,-100) 3(100,0) 4(100,-100) 5(200,0) 6(200,-100) 7(300,0) 8(300,-100) 9(400,0) 10(400,-100)
  silkscreen extent -60,-150 460,50
"Header 5x.05" [mil]
  oval 40x60 hole 22: 1(0,0) 2(50,0) 3(100,0) 4(150,0) 5(200,0)
  silkscreen extent -25,-38 225,38
HS1101 [mil] "Humirel sensor"
  round 60 hole 30: 1(0,0) 2(200,0)
  silkscreen extent -100,-200 300,200
MA05A [mm] "SOT-23/SC-74A; 5 Leads; Body 3 x 3 mm, inc. leads (LxW max)"
  rect 0.5x1.45 smd: 1(-0.95,-1.075) 2(0,-1.075) 3(0.95,-1.075) 4(0.95,1.075) 5(-0.95,1.075)
  silkscreen extent -2.37,-2.2 1.6,2.2
"MTA-100-4 Shrouded" [mil] "AMP 644486-4"
  round 0 hole 78 unplated: 0(-342,-124) 0(42,-124)
  round 75 hole 42: 1(0,0) 2(-100,0) 3(-200,0) 4(-300,0)
  silkscreen extent -392,-175 92,135
NSO14 [mm] "Small Outline; 14 Leads; Body Width 3.9 mm; Pitch 1.27 mm"
  rect 0.6x2.2 smd: 1(-3.81,-2.6) 2(-2.54,-2.6) 3(-1.27,-2.6) 4(0,-2.6) 5(1.27,-2.6) 6(2.54,-2.6) 7(3.81,-2.6) 8(3.81,2.6) 9(2.54,2.6) 10(1.27,2.6) 11(0,2.6) 12(-1.27,2.6) 13(-2.54,2.6) 14(-3.81,2.6)
  silkscreen extent -4.78,-2.72 4.38,1.1
P600 [mil] "Axial .35x.35-.052"
  round 100 hole 60: 1(0,0) 2(700,0)
  silkscreen extent 40,-175 660,175
PLB08F3 [mil] "Positronic PLB08 fem vert"
  round 175 hole 123: 0(-245,0) 0(836,0)
  round 125 hole 80: 1(591,99) 2(394,99) 3(197,100) 4(0,99) 5(591,-98) 6(394,-98) 7(197,-98) 8(0,-98)
  silkscreen extent -366,-305 958,305
PLB12F3 [mil] "Positronic PLB12 fem vert"
  round 175 hole 123: 0(-245,0) 0(1230,0)
  round 125 hole 80: 1(985,99) 2(788,99) 3(591,99) 4(394,99) 5(197,100) 6(0,99) 7(985,-98) 8(788,-98) 9(591,-98) 10(394,-98) 11(197,-98) 12(0,-98)
  silkscreen extent -366,-305 1351,305
"Resistor 5W - ceramic" [mil]
  round 72 hole 32: 1(0,0) 2(200,0)
  silkscreen extent -150,-50 350,50
"Shunt PCB-BH-50-50" [mil] "Canadian Shunt"
  round 325 hole 200: 1(-810,0) 4(810,0)
  round 150 hole 100: 2(-550,0) 3(550,0)
  Top Layer region: 1012.5,25 950,25 950,-25 1012.5,-25
  Top Layer region: -1012.5,-25 -950,-25 -950,25 -1012.5,25
  silkscreen extent -450,0 450,0
SMA [mm] "DO-214-AC/SMA; 2 C-Bend Leads; Body 5 x 2.7 mm, inc. leads (LxW)"
  rect 2.4x1.8 smd: 1(-2.05,0) 2(2.05,0)
  silkscreen extent -3.65,-1.3 3.95,1.3
SO-8 [mm] "Plastic Small Outline; 8 Leads; Body Width 3.9 mm"
  rect 0.55x2.2 smd: 1(-1.905,-2.6) 2(-0.635,-2.6) 3(0.635,-2.6) 4(1.905,-2.6) 5(1.905,2.6) 6(0.635,2.6) 7(-0.635,2.6) 8(-1.905,2.6)
  silkscreen extent -2.85,-2.72 2.5,1.1
SO-G3/C2.5 [mm]
  rect 0.9x0.95 smd: 1(-0.95,-1.25) 2(0.95,-1.25) 3(0,1.25)
  silkscreen extent -2.08,-1.37 1.3,1.25
SO-G6/Z2.8 [mm]
  rect 0.35x1.25 smd: 1(-0.65,-0.775) 2(0,-0.775) 3(0.65,-0.775) 4(0.65,0.775) 5(0,0.775) 6(-0.65,0.775)
  silkscreen extent -2.02,-1.8 1.25,1.8
SO-G8 [mm]
  rect 0.6x2.2 smd: 1(-1.905,-2.6) 2(-0.635,-2.6) 3(0.635,-2.6) 4(1.905,-2.6) 5(1.905,2.6) 6(0.635,2.6) 7(-0.635,2.6) 8(-1.905,2.6)
  silkscreen extent -2.88,-2.72 2.5,1.1
SOT23 [mm] "SOT-23; 3 Leads; Body 3.0 x 2.5 mm, inc. leads (LxW max)"
  rect 0.85x1 smd: 1(-0.95,-1.2) 2(0.95,-1.2) 3(0,1.2)
  silkscreen extent -2.05,-1.32 1.27,1.2
SOT23-5 [mm] "SOT-23/SC-74A; 5 Leads; Body 3 x 3 mm, inc. leads (LxW max)"
  rect 0.55x1.45 smd: 1(-0.95,-1.075) 2(0,-1.075) 3(0.95,-1.075) 4(0.95,1.075) 5(-0.95,1.075)
  silkscreen extent -2.42,-2.2 1.65,2.2
SSO-G24/P.65 [mm]
  rect 0.4x2.15 smd: 1(-3.575,-3.275) 2(-2.925,-3.275) 3(-2.275,-3.275) 4(-1.625,-3.275) 5(-0.975,-3.275) 6(-0.325,-3.275) 7(0.325,-3.275) 8(0.975,-3.275) 9(1.625,-3.275) 10(2.275,-3.275) 11(2.925,-3.275) 12(3.575,-3.275) 13(3.575,3.275) 14(2.925,3.275) 15(2.275,3.275) 16(1.625,3.275) 17(0.975,3.275) 18(0.325,3.275) 19(-0.325,3.275) 20(-0.975,3.275) 21(-1.625,3.275) 22(-2.275,3.275) 23(-2.925,3.275) 24(-3.575,3.275)
  silkscreen extent -4.45,-3.4 4.25,1.8
"Terminal 10AWG crimp" [mil] "AMP 794037-1 wire to pcb"
  round 200 hole 148: 1(0,0)
  silkscreen extent -115,-115 115,115
"Terminal - screw" [mil] "Keystone #8199"
  round 125 hole 76: 1(0,0) 1(0,-197) 1(0,-394) 1(276,-394) 1(276,-197) 1(276,0)
  silkscreen extent -15,-450 291,55
"TO220 576602" [mil] "Aavid 576602T00000"
  round 175 hole 122: 0(-475,-350) 0(0,25) 0(475,-350)
  silkscreen extent -475,-250 475,25
TO-220AB [mm] "TO, Thru-Hole, Vertical, Heatsink Mounted; 3 In-Line Leads; Pitch 2.54 mm"
  rect 1.6x1.6 hole 1: 1(-2.54,0)
  round 1.6 hole 1: 2(0,0) 3(2.54,0)
  silkscreen extent -5.35,-1.85 5.35,2.85
XPort [mil] "Lantronix XPort"
  round 0 hole 128: 0(-350,417) 0(-350,-67)
  round 65 hole 35: 1(0,0) 2(-100,50) 3(0,100) 4(-100,150) 5(0,200) 6(-100,250) 7(0,300) 8(-100,350)
  round 100 hole 63: 9(119,491) 9(119,-141)
  silkscreen extent -777,-184 558,534

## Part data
C1 C1_1 C1_2 C1_3 C1_4 C1_5 C1_6 C1_7 C1_8 C2 C3 C4 C5 C6 C7 C8 C9 C10 C11 C12 C13 C14 C15 C16 C17 C18 C19 C22 C23 C24 C25 C26 C27 C28 C29 C30 C31 C32 C33 C34 C35 C36 C37 C38 C39 C40 C41 C42 C43 C44 C46 C47 C48 C52 C53 C54: "Ceramic Chip Capacitor - Standard"
C20 C21: library part C0402, "Ceramic Chip Capacitor - Standard"
C45 C49 C50 C51: "Polarized Capacitor (Axial)"
D1: library part Diode, "Default Diode"
D2: "Zener Diode"
D3 D4: library part BAS40DW-06
D5 D6: "Silicon AF Schottky Diode for High-Speed Switching"
F1 F2: library part "Fuseclip Mini vert"
JP1_1 JP1_2 JP1_3 JP1_4 JP1_5 JP1_6 JP1_7 JP1_8: library part "Header 5", "Header, 5-Pin"
JP9: library part "HEADER 8F SHROUDED"
JP10: library part "Header 3 Shrouded"
JP11: "Header, 5-Pin, Dual row"
JP12 JP13: "Header, 2-Pin"
JP14 JP15 JP16 JP17 JP18 JP19: library part "HEADER 5X1"
JP20: library part "HEADER 12F SHROUDED"
L1 L2 L3: library part Inductor, "Inductor"
L4: "Magnetic-Core Inductor"
Q1 Q2 Q3 Q4 Q5 Q6 Q7 Q8 Q14 Q16: "NPN General-purpose Transistor"
Q9 Q10 Q11 Q12: library part IRF7324, "HEXFET Power MOSFET"
Q13 Q15 Q17 Q19 Q21 Q22: "General Purpose Transistor PNP Silicon"
Q18 Q20 Q23 Q24 Q25 Q26 Q31 Q32 Q33 Q35: "General Purpose Transistor NPN Silicon"
Q27 Q28 Q29 Q30 Q36 Q37: "HEXFET Power MOSFET"
Q34: library part BSS84, "P-Channel Enhancement Mode Vertical DMOS FET"
R1 R1_1 R1_2 R1_3 R1_4 R1_5 R1_6 R1_7 R1_8 R3 R4 R5 R6 R9 R12 R13 R14 R15 R16 R21 R22 R25 R26 R29 R30 R33 R34 R35 R36 R37 R38 R39 R40 R43 R44 R46 R47 R48 R49 R50 R51 R52 R53 R54 R55 R56 R57 R58 R59 R60 R61 R62 R63 R64 R65 R66 R67 R68 R69 R70 R71 R72 R73 R76 R77 R80 R81 R84 R85 R88 R89 R90 R91 R92 R93 R94 R95 R96 R97 R98 R99 R100 R101 R102 R103: "Thick Film Chip Resistor, 1 Ohm to 10M Ohm Range, 5% Tolerance, 0805 Size, 0.125 W"
R2 R7 R8 R10 R11 R17 R18 R41 R42 R45: library part Res1, "Resistor"
R19 R20 R23 R24 R27 R28 R31 R32 R74 R75 R78 R79 R82 R83 R86 R87: library part "Resistor 5W ceramic"
U1 U2: library part MSP430F133, "Ultra Low Power 16 bit Mixed Signal uC"
U1_1 U1_2 U1_3 U1_4 U1_5 U1_6 U1_7 U1_8: library part LM74CIM
U3: library part LM7131ACM5, "Tiny High-Speed Single-Supply Operational Amplifier"
U4: "Lithium Battery Protection Analog Front End"
U5 U6: "Tiny High-Speed Single-Supply Operational Amplifier"
U7: library part LTC1155CS8
U8: "3-to-8 Line Decoder"
U10: library part TC962COE
U11: "Low-Cost, Ultra-Small, 3µA Single-Supply Comparator"
Y1 Y2: library part XTAL, "Crystal Oscillator"

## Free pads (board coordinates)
  round 0 hole 275 unplated: 0(1151.74,4298.37) 1(-1151.74,4298.37) 2(-3146.63,3146.63) 3(-4298.37,1151.74) 4(-4298.37,-1151.74) 5(-3146.63,-3146.63) 6(-1151.74,-4298.37) 7(1151.74,-4298.37) 8(3146.63,-3146.63) 9(4298.37,-1151.74) 10(4298.37,1151.74) 11(3146.63,3146.63) 12(1139.39,1973.48) 13(-1139.39,-1973.48)

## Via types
v1: diameter 25, hole 15, Top Layer to Bottom Layer, 205 vias
v2: diameter 40, hole 22, Top Layer to Bottom Layer, 24 vias
v3: diameter 75, hole 50, Top Layer to Bottom Layer, 16 vias

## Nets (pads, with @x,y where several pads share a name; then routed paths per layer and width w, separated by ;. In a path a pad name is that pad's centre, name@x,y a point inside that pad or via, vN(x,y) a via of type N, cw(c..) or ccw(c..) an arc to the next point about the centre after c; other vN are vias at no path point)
+3DL: C1.2 C5.1 JP10.1 JP23.1 L1.1 Q14.1 Q16.1 R7.1 R100.2 R102.1 U1.1 | length 7542.1
  Top Layer w8: Q14.1@887.4,2947.24 925,2984.84 925,3300 887.4,3337.6 Q16.1@887.4,3347.24 ; 925,3000 1212.5,3000 ; C1.2@2812.6,287.4 C1.2@2812.6,300 C5.1@2812.6,400 ; 2875,206.25 2877.36,197.64 U1.1@2904.53,197.64 ; R102.1@3000,-337.3 3050,-387.3 R100.2@3200,-387.3 ; R7.1@3025.59,650.59 JP23.1@3136.81,650.59 ; v1(3475,712.5) 3500,737.5 3500,775 L1.1@3512.5,775
  Top Layer w20: JP10.1@1150,3250 1212.5,3187.5 1212.5,2925 1200,2912.5 1200,2812.5 1250,2762.5 1662.5,2762.5 2275,2150 2837.5,2150 2862.5,2125 2862.5,1425 2887.5,1400 3262.5,1400 3562.5,1100 3562.5,825 L1.1@3512.5,775 ; C1.2@2812.6,287.4 2825,287.5 2825,243.75 v1(2862.5,206.25) 2875,206.25
  Bottom Layer w8: v1(2862.5,206.25) 2881.25,187.5 3150,187.5 3212.5,137.5 3212.5,-300 3150,-362.5 v1(3150,-387.5) ; 3075,187.5 3075,675 3125,725 3462.5,725 v1(3475,712.5)
  other v1: 3075,650
+3DU: C2.2 C6.1 C16.2 C35.2 JP14.1 JP15.1 JP16.1 JP17.1 JP18.1 JP19.1 JP24.1 L2.1 R8.1 R42.2 R44.2 R51.1 R55.2 R98.1 U2.1 U6.5 U8.6 U8.16 | length 8840.2
  Top Layer w8: JP19.1@-1950,2800 JP17.1@-1950,3300 ; JP16.1@-1500,2800 JP14.1@-1500,3300 -1250,3550 -950,3550 -812.6,3550 L2.1@-775,3512.4 -775,3493.75 -725,3493.75 v1(-712.5,3475) ; R8.1@-650.59,3025.79 JP24.1@-650.59,3136.81 ; R8.1@-649.8,3025 R8.1@-649.8,3031.45 ; C6.1@-400,2812.6 -387.5,2825 -312.5,2825 C2.2@-300,2812.6 ; -250.1,4774.8 C35.2@-350,4774.8 -412.5,4712.3 -412.5,4675 -312.5,4575 -312.5,4275 -287.5,4250 262.5,4250 275,4237.5 R51.1@275,3837.4 75,3837.45 -162.5,3837.5 -175,3850 U8.16@-175,3902.36 U8.16@-175,3862.5 ; U6.5@-249.9,4742.32 -250,4793.75 -250,4837.4 R55.2@-237.4,4850 ; -206.25,2875 -197.64,2877.36 U2.1@-197.64,2904.53 ; U8.6@75,3697.64 75,3837.5 ; v1(237.5,3262.5) 256.25,3262.5 268.95,3249.8 R98.1@275,3249.8 ; v1(625,3225) 643.75,3225 R42.2@662.6,3243.85 ; R44.2@662.6,2850 612.5,2900.1 612.5,2987.5 587.5,3012.5 587.5,3087.5 600,3100 837.5,3100 850,3112.5 850,3187.5 837.5,3200 700,3200 662.6,3237.4 R42.2@662.6,3250
  Top Layer w20: C2.2@-287.4,2812.6 -225,2875 -206.25,2875 ; C16.2@-275,3837.5 -200,3837.5 U8.16@-175,3862.5 ; v1(-225,3812.5) -225,3837.5 ; v1(75,3637.5) U8.6@75,3697.64
  Bottom Layer w8: JP18.1@-1950,3050 -1900,3100 -1550,3100 JP15.1@-1500,3050 ; v1(-350,2825) -387.5,2862.5 -387.5,3037.5 -425,3075 v1(-650,3075) -700,3075 -725,3100 -725,3462.5 v1(-712.5,3475) -712.5,3487.5 -387.5,3812.5 v1(-225,3812.5) ; v1(75,3637.5) 237.5,3475 v1(237.5,3262.5) 250,3250 600,3250 v1(625,3225)
+3H: C48.2 C49.1 C50.1 C51.1 L4.2 R101.2 U7.4 U9.2 | length 5290.6
  Top Layer w8: R101.2@3300,-387.3 3312.7,-387.3 3325,-362.5 3337.5,-362.5 3450,-250 4187.5,-250 4212.5,-225 4212.5,37.5 U9.2@4125,125 ; L4.2@3405,1957.5 L4.2@3405,2050 ; 3837.5,1800 4062.5,2025 U7.4@4097.64,2025
  Top Layer w20: L4.2@3405,1957.5 3562.5,1800 3837.5,1800 3862.5,1775 3862.5,437.5
  Top Layer w50: C51.1@3125,1900 C50.1@3125,2050 L4.2@3405,2050 3405,2155 3575,2325 C49.1@3875,2325 ; C48.2@3800,437.4 3837.5,437.5 3937.5,437.5 4125,250 U9.2@4125,125
+3L: C3.2 C7.1 C9.2 L1.2 R9.1 R10.1 R94.2 R95.2 U1.64 U3.18 U5.5 | length 13523.1
  Top Layer w8: R95.2@25,-4675 R94.2@125,-4675 ; v1(537.5,-4987.5) 575,-5025 661.55,-5025 1939.58,-4682.55 2093.66,-4593.59 2093.75,-4593.54 ; 2093.75,-4593.75 2100,-4587.5 v1(2100,-4531.25) ; v1@2200.41,-4531.96 3085.42,-4021 3593.84,-3512.59 ; v1(2425,-375) 2462.5,-337.5 v1(2462.5,325) ; U5.5@2467.32,-612.6 2562.5,-612.6 C9.2@2575,-625.1 ; 2500,-612.6 v1(2500,-587.5) ; v1(2750,-475) 5075,-475 5100,-500 5100,-671.43 4752.44,-1968.53 4081.02,-3131.47 4012.49,-3200 v1(3900,-3200) ; v1(2975,350) 2975,312.5 2977.36,310.14 U1.64@2977.36,270.47 ; U3.18@3178.94,962.2 3274.8,962.2 C3.2@3287.6,975 3287.6,968.65 3325,931.25 3325,912.3 R9.1@3362.3,875 ; L1.2@3437.6,775 R10.1@3362.5,775 3362.3,775.2 R9.1@3362.3,875 ; C7.1@3437.6,875 R9.1@3362.3,875 ; 3593.75,-3512.5 3593.75,-3506.25 v1(3600,-3500)
  Bottom Layer w8: v1(75,-4675) 400,-4675 525,-4800 525,-4975 v1(537.5,-4987.5) ; v1(2100,-4531.25) v1(2200,-4531.25) ; v1(2462.5,325) 2475,337.5 2956.25,337.5 2968.75,350 v1(2975,350) ; v1(2500,-587.5) 2500,-550 2400,-450 2400,-400 v1(2425,-375) 2650,-375 v1(2750,-475) ; v1@2975.5,350 3050.5,425 3050,687.5 3112.5,750 3299.5,750 v1(3362.5,812.5) ; v1(3600,-3500) v1(3900,-3200)
+3U: C4.2 C8.1 L2.2 Q35.1 R63.1 R64.1 U2.64 U4.18 | length 10322.5
  Top Layer w8: U4.18@-962.21,3178.94 -962.21,3274.8 C4.2@-975,3287.6 -937.6,3325 -918.75,3325 -881.35,3362.4 R63.1@-875,3362.4 C8.1@-875,3437.6 ; v1(-750,-2200) -825,-2275 -1550,-2275 -1575,-2250 -1575,1900 -1375,2100 -1375,2475 -1350,2500 -1350,3350 -1275,3425 -887.6,3425 C8.1@-875,3437.6 ; v1(-625,-2200) 425,-2200 762.5,-1862.5 950,-1862.5 993.65,-1906.15 Q35.1@993.65,-1907.04 ; -312.5,2975 -362.5,2975 -387.5,3000 -500,3000 -518.75,2981.25 -693.75,2981.25 -712.5,3000 -712.5,3112.5 -725,3125 -725,3312.5 R64.1@-775,3362.5 L2.2@-775,3437.6 C8.1@-875,3437.6 ; -310.14,2977.36 U2.64@-270.47,2977.36
  Bottom Layer w8: v1(-750,-2200) v1(-625,-2200)
/BATT_EN1: D3.1 JP9.4 | length 3738
  Top Layer w8: D3.1@-311.02,-4598.82 -300,-4600 -300,-4550 -287.5,-4537.5 v1(337.5,-4537.5) ; v1(500,-4537.5) 500,-5000 550,-5050 664.85,-5050 1949.23,-4705.85 2155.11,-4586.98 ; 2154.26,-4585.51 JP9.4@2154.26,-3929.29
  Bottom Layer w8: v1(337.5,-4537.5) v1(500,-4537.5)
/BATT_EN2: D3.2 JP20.5 | length 6435.4
  Top Layer w8: D3.2@-311.02,-4624.41 -350.59,-4624.41 -362.5,-4612.5 -362.5,-4525 -350,-4512.5 v1(312.5,-4512.5) ; v1(475,-4512.5) 475,-5012.5 537.5,-5075 668.14,-5075 1958.88,-4729.15 3116.12,-4061.01 3660.25,-3516.88 ; 3659.19,-3515.81 JP20.5@3659.19,-2228.1
  Bottom Layer w8: v1(312.5,-4512.5) v1(475,-4512.5)
/BATT_EN3: D3.4 JP20.6 | length 6736
  Top Layer w8: D3.4@-250,-4650 -250,-4687.5 -262.5,-4700 -375,-4700 -387.5,-4687.5 -387.5,-4500 -375,-4487.5 v1(337.5,-4487.5) ; v1(450,-4487.5) 450,-5025 525,-5100 671.43,-5100 1968.53,-4752.44 3131.47,-4081.02 3830.29,-3382.2 JP20.6@3830.29,-2325.74
  Bottom Layer w8: v1(337.5,-4487.5) v1(450,-4487.5)
/BATT_ON: JP13.2 U2.20 | length 10763.8
  Top Layer w8: v1(-1775,2200) -1750,2175 -1750,-2950 -475,-4225 -475,-4875 -450,-4900 -300,-4900 JP13.2@-250,-4850 ; v1(-600,2225) -600,2512.5 -575,2537.5 200,2537.5 v1(212.5,2525) ; U2.20@170.47,3036.42 223.92,3036.42 225,3037.5 v1(237.5,3025)
  Bottom Layer w8: v1(-1775,2200) -1762.5,2212.5 -1562.5,2212.5 -1550,2200 -625,2200 v1(-600,2225) ; v1(212.5,2525) 225,2537.5 225,3012.5 v1(237.5,3025)
/COMMS_OFF: JP11.9 R102.2 U1.19 | length 14634
  Top Layer w8: JP11.9@-2825,-2250 -2675,-2400 -2325,-2400 -500,-4225 -500,-5100 -475,-5125 337.5,-5125 v1(362.5,-5100) ; v1(462.5,-5100) 487.5,-5125 674.72,-5125 1978.18,-4775.74 3146.82,-4101.02 4101.02,-3146.82 4775.74,-1978.18 5125,-674.72 5125,-475 5100,-450 3150,-450 3125,-425 2968.75,-424.25 2953.5,-409 2953.5,-309 R102.2@3000,-262.5 3016.73,-245.77 U1.19@3016.73,-170.47
  Bottom Layer w8: v1(362.5,-5100) v1(462.5,-5100)
/ENETOFF: R100.1 U1.28 U7.5 | length 4040.8
  Top Layer w8: U1.28@3193.9,-170.47 3193.9,-306.4 3250,-362.5 3250,-412.5 3262.5,-425 3375,-425 3412.5,-387.5 4225,-387.5 4250,-362.5 4250,200 3900,550 3900,1700 4225,2025 U7.5@4302.36,2025
/RST_ENET: R101.1 U1.29 U9.3 | length 1143.2
  Top Layer w8: R101.1@3300,-312.5 3262.5,-275 3237.5,-275 3213.58,-251.08 3213.58,-123.92 3225,-112.5 3287.5,-112.5 3300,-125 3675,-125 3875,75 U9.3@4025,75
/TEMP_EN: R51.2 U2.44 U8.4 | length 1169.2
  Top Layer w8: U2.44@-118.9,3345.47 -118.9,3306.4 -125.3,3300 -212.5,3300 -237.5,3325 -237.5,3575 -225,3587.5 -125,3587.5 -100,3612.5 -25,3612.5 ; U8.4@-25,3697.64 -25,3612.5 ; R51.2@275,3762.6 262.6,3762.6 250,3750 250,3625 237.5,3612.5 -25,3612.5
